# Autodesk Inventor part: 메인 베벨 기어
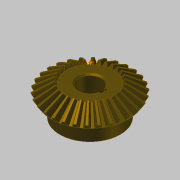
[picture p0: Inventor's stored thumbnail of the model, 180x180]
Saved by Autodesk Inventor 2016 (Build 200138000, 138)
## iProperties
Created: 2016-04
Part Number: 메인 베벨 기어
Material: 강철, 탄소
Document SubType Name: Modeling
Designer: mdu
Categories: <?xml version="1.0" encoding="UTF-16"?> <MemberInstance><Categories><FamilyTemplate><FamilyTemplateParameter ValueType="xs:double" Id="1" ObjectReferenceKey="da
Mass: 269.926 g
Surface Area: 108.837 cm^2
Volume: 34.2981 cm^3
Density: 7.87 g/cm^3
Appearance: 얼룩무늬
CustomPartVersion: 1
Author: mdu
Revision Number: 1
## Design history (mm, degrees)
node "맨 위 점"
node "메쉬 평면2"
sketch "톱니 본체 스케치"
  geometry: L1 (0, 0)-(28.669, -21.997); L2 (28.669, -21.997)-(31.109, -18.336); L3 (31.109, -18.336)-(0, 0); L4 (30, -20)-(0, 0); L5 (17.219, -13.212)-(18.685, -11.013); L6 (28.669, -21.997)-(17.219, -13.212); L7 (31.109, -18.336)-(18.685, -11.013); L8 (0, -39.387)-(0, 6.564) reference; L9 (0, -20)-(31.109, -20)
  constraints: 16 end point, 4 point on line, 3 perpendicular, 2 collinear, 1 horizontal alignment, 1 vertical alignment
  dimensions: "d0" = 60 diameter of L4.start L8 (= da_de); "d1" = 57.33744 diameter of L1.end L8 (= da_dfe); "d2" = 62.2188 diameter of L2.end L8 (= da_dae); "d3" = 14.4 distance between parallel lines of L2 L5 (= da_b); "d4" = 18.3359 vertical distance of L2.end L1.start (= da_ve)
revolve "톱니 본체" sketch "톱니 본체 스케치" stored, may be unused: angle "d5" = 90 deg
node "시작점"
node "톱니 평면"
sketch "시작 스케치"
  geometry: L1 (0, -23.505)-(0, 10.645) reference; L2 (-0.709, -2.928)-(0.709, -2.928); A1 r 19.188 centre (-19.457, -7.014) between (-0.709, -2.928) and (-3.232, 3.229); A2 r 19.188 centre (19.457, -7.014) between (3.232, 3.229) and (0.709, -2.928); A3 r 57.403 centre (0, -54.083) between (3.232, 3.229) and (-3.232, 3.229); 1 further point
  constraints: 6 point on circle, 3 centre point, 3 symmetric about line, 2 end point, 1 coincident, 1 perpendicular, 1 other
  dimensions: "d7" = 19.18795 radius of A1 (= fd_rr); "d8" = 19.45712 horizontal distance of point (0, -54.083) A1.centre (= fd_x); "d9" = 47.06905 vertical distance of point (0, -54.083) A1.centre (= fd_y); "d57" = 57.40327 radius of A3 (= 0.5 x fd_dva + 0.3 x da_he); "d58" = 51.15527 distance from line of A3.centre L2 (= 0.5 x fd_dva - 1.12 x da_he)
node "끝점"
  node "끝 평면"
sketch "3D 스케치 오른쪽"
  node "Helical Curve Right" dims "d65" = 229.90621 (computed from da_dm, da_delta, da_beta), "d66" = 31.5, "d67" = 60 (= da_de), "d68" = -9.82794 (= -da_delta), "d69" = 8.10972 (computed from fd_loft, da_delta)
node "끝 평면 오른쪽"
sketch "끝 스케치 오른쪽"
  geometry: L1 (0, -41.54)-(0, 13.178) reference; L2 (-0.422, -1.69)-(0.422, -1.69); A1 r 11.427 centre (-11.587, -4.123) between (-0.422, -1.69) and (-1.925, 1.977); A2 r 11.427 centre (11.587, -4.123) between (1.925, 1.977) and (0.422, -1.69); A3 r 34.184 centre (0, -32.153) between (1.925, 1.977) and (-1.925, 1.977); 1 further point
  constraints: 6 point on circle, 3 centre point, 3 symmetric about line, 2 end point, 1 coincident, 1 perpendicular, 1 other
  dimensions: "d70" = 11.58699 horizontal distance of A3.centre A1.centre (computed from fd_x, fd_ratio); "d71" = 28.03028 vertical distance of point (0, -32.153) A1.centre (computed from fd_y, fd_ratio); "d72" = 11.4267 radius of A1 (computed from fd_rr, fd_ratio); "d73" = 30.46369 distance from line of point (0, -32.153) L2 (computed from d58, fd_ratio); "d74" = 34.18446 radius of A3 (computed from d57, fd_ratio)
feature "로프트 오른쪽" sketch "끝 스케치 오른쪽" dims "d75" = 0, "d77" = 0, "d79" = 0, "d80" = 90 deg, "d85" = 20, "d92" = 90 deg, "d93" = 90 deg, "da_teethtype" = 0 [user parameter]
sketch "3D 스케치 왼쪽"
  node "Helical Curve Left" dims "d26" = 229.90621 (computed from da_dm, da_delta, da_beta), "d27" = 8.10972 (computed from fd_loft, da_delta), "d28" = 60 (= da_de), "d29" = -9.82794 (= -da_delta)
node "끝 평면 왼쪽"
sketch "끝 스케치 왼쪽" dims "d56" = 10.3728 (derived)
  geometry: L1 (0, -43.753)-(0, 15.405) reference; L2 (-0.422, -1.678)-(0.422, -1.678); A1 r 11.427 centre (-11.587, -4.111) between (-0.422, -1.678) and (-1.925, 1.988); A2 r 11.427 centre (11.587, -4.111) between (1.925, 1.988) and (0.422, -1.678); A3 r 34.184 centre (0, -32.142) between (1.925, 1.988) and (-1.925, 1.988); 2 further points; 1 other entity
  constraints: 6 point on circle, 3 centre point, 3 symmetric about line, 2 end point, 1 coincident, 2 other
  dimensions: "d30" = 11.4267 radius of A1 (computed from fd_rr, fd_ratio); "d31" = 11.58699 horizontal distance of point (0, -32.142) A1.centre (computed from fd_x, fd_ratio); "d32" = 28.03028 vertical distance of A1.centre point (0, -32.142) (computed from fd_y, fd_ratio); "d61" = 34.18446 radius of A3 (computed from d57, fd_ratio); "d62" = 30.46369 distance from line of point (0, -32.142) L2 (computed from d58, fd_ratio)
feature "로프트 왼쪽" sketch "끝 스케치 왼쪽" dims "d35" = 0, "d37" = 0, "d39" = 0, "d40" = 90 deg, "d84" = 10, "d90" = 90 deg, "d91" = 90 deg, "da_teethtype" = 0 [user parameter]
sketch "본체 스케치"
  geometry: L1 (0, -35.038)-(0, -19.531) reference; L2 (28.669, -21.997)-(17.219, -13.212) reference; L3 (17.219, -13.212)-(0, -13.212); L4 (28.669, -21.997)-(0, -21.997)
  constraints: 4 end point, 2 perpendicular, 2 point on line
revolve "본체 고정" sketch "본체 스케치" stored, may be unused: angle "d46" = 90 deg
feature "피치 지름" dims angle "d47" = 90 deg
sketch "스케치8"
  geometry: C1 r 22.5 at (0, 0); 1 further point
  constraints: 1 centre point, 1 coincident
  dimensions: "d94" = 45 diameter of C1
extrude "돌출1" join sketch "스케치8" distance "d95" = 13; taper "d96" = 0 deg
sketch "스케치9"
  geometry: 1 further point
hole "구멍1" sketch "스케치9" at (0, 0) diameter "d97" = 17; stored, may be unused: countersink angle "d101" = 90 deg, drill point angle "d103" = 118 deg; dims "d98" = 6, "d99" = 4, "d100" = 2, "d102" = 8
sketch "스케치10"
  geometry: L1 (8.124, 2.5)-(10.8, 2.5); L2 (10.8, 2.5)-(10.8, -2.5); L3 (10.8, -2.5)-(8.124, -2.5); A1 r 8.5 centre (0, 0) between (8.124, 2.5) and (8.124, -2.5) reference; 1 further point
  constraints: 6 end point, 2 parallel, 2 point on circle, 1 horizontal, 1 perpendicular
  dimensions: "d104" = 5 distance of L1.end L2.end; "d112" = 19.3 dimension on A1 L2
extrude "돌출2" cut sketch "스케치10" stored distance "d106" = 10; taper "d107" = 0 deg
chamfer "모따기1" distance "d108" = 1; stored, may be unused: second distance "d109" = 2, angle "d110" = 45 deg
fillet "모깎기1" dims "d111" = 2
body "Solid1"
feature "로프트" dims "d17" = 0, "d18" = 90 deg, "d19" = 0, "d20" = 90 deg, "d89" = 0, "da_teethtype" = 0 [user parameter]
pattern_circular "원형 패턴" dims angle "d22" = 360 deg, "d88" = 0, "da_teethtype" = 0 [user parameter]
pattern_circular "원형 패턴 오른쪽" dims angle "d82" = 360 deg, "da_teethtype" = 0 [user parameter]
pattern_circular "원형 패턴 왼쪽" dims angle "d42" = 360 deg, "da_teethtype" = 0 [user parameter]
sketch "끝 스케치"
  geometry: L1 (0, -15.359)-(0, 6.983) reference; L2 (-0.422, -1.69)-(0.422, -1.69); A1 r 11.427 centre (-11.587, -4.123) between (-0.422, -1.69) and (-1.925, 1.977); A2 r 11.427 centre (11.587, -4.123) between (1.925, 1.977) and (0.422, -1.69); A3 r 34.184 centre (0, -32.153) between (1.925, 1.977) and (-1.925, 1.977); 1 further point
  constraints: 6 point on circle, 3 centre point, 3 symmetric about line, 2 end point, 1 coincident, 1 other
  dimensions: "d12" = 11.4267 radius of A1 (computed from fd_rr, fd_ratio); "d15" = 11.58699 horizontal distance of A1.centre point (0, -32.153) (computed from fd_x, fd_ratio); "d16" = 28.03028 vertical distance of A1.centre point (0, -32.153) (computed from fd_y, fd_ratio); "d59" = 34.18446 radius of A3 (computed from d57, fd_ratio); "d60" = 30.46369 distance from line of A3.centre L2 (computed from d58, fd_ratio)
sketch "Sketch6"
  geometry: L1 (30, -20)-(0, 0) reference; L2 (0, -37.8)-(0, 6.3) reference
body "Srf1"
other parameters: "da_b" = 14.4 [user parameter; used in 2 equation terms], "da_de" = 60 [user parameter; used in 4 equation terms], "da_dae" = 62.2188 [user parameter; used in 2 equation terms], "da_dfe" = 57.33744 [user parameter; used in 1 equation term], "da_le" = 36.05551 [user parameter; used in 1 equation term], "da_omega" = 90 deg [user parameter; used in 1 equation term], "da_beta" = 0 [user parameter; used in 2 equation terms], "da_delta" = 9.82794 [user parameter; used in 8 equation terms], "da_alpha" = 20 deg [user parameter; used in 2 equation terms], "da_he" = 4.4 [user parameter; used in 4 equation terms], "da_ve" = 18.3359 [user parameter; used in 1 equation term], "fd_dv" = 108.16654 (computed from da_de, da_delta) [user parameter; used in 1 equation term], "fd_dva" = 112.16654 (computed from da_dae, da_delta) [user parameter; used in 3 equation terms], "fd_dvb" = 101.6433 (computed from fd_dv, da_alpha) [user parameter; used in 2 equation terms], "da_zv" = 540.83269 [user parameter; used in 1 equation term], "fd_loft" = 14.62 (= da_b + 0.05 x da_he) [user parameter; used in 4 equation terms], "fd_ratio" = 5.95514 (computed from da_le, fd_loft) [user parameter; used in 15 equation terms], "fd_rr" = 19.18795 (computed from fd_dd, fd_dvb) [user parameter; used in 6 equation terms], "fd_angle" = 0.29367 (computed from da_zv) [user parameter; used in 4 equation terms], "fd_x1" = 1.58802 (computed from da_dvw, fd_angle) [user parameter; used in 1 equation term], "fd_y1" = 54.05995 (computed from da_dvw, fd_angle) [user parameter; used in 1 equation term], "fd_x2" = 17.8691 (computed from fd_rr, fd_angle2, fd_angle) [user parameter; used in 1 equation term], "fd_y2" = 6.9909 (computed from fd_rr, fd_angle2, fd_angle) [user parameter; used in 1 equation term], "fd_x" = 19.45712 (= fd_x1 + fd_x2) [user parameter; used in 4 equation terms], "fd_y" = 47.06905 (= fd_y1 - fd_y2) [user parameter; used in 4 equation terms], "fd_angle2" = 3.43555 (computed from fd_dvb, fd_dd, da_alpha) [user parameter; used in 2 equation terms], "fd_dd" = 108.64654 (= fd_dva - 0.8 x da_he) [user parameter; used in 2 equation terms], "da_dvw" = 108.16654 [user parameter; used in 2 equation terms], "d11" = 14.62 (= fd_loft), "da_dm" = 48.01848 [user parameter; used in 2 equation terms], "da_x" = 0 [user parameter], "da_m" = 2 [user parameter], "d48" = 0, "d49" = 0, "d50" = 90 deg (= da_omega), "d51" = 6 deg (computed from da_z), "d52" = 0, "d53" = 0, "d54" = 0
